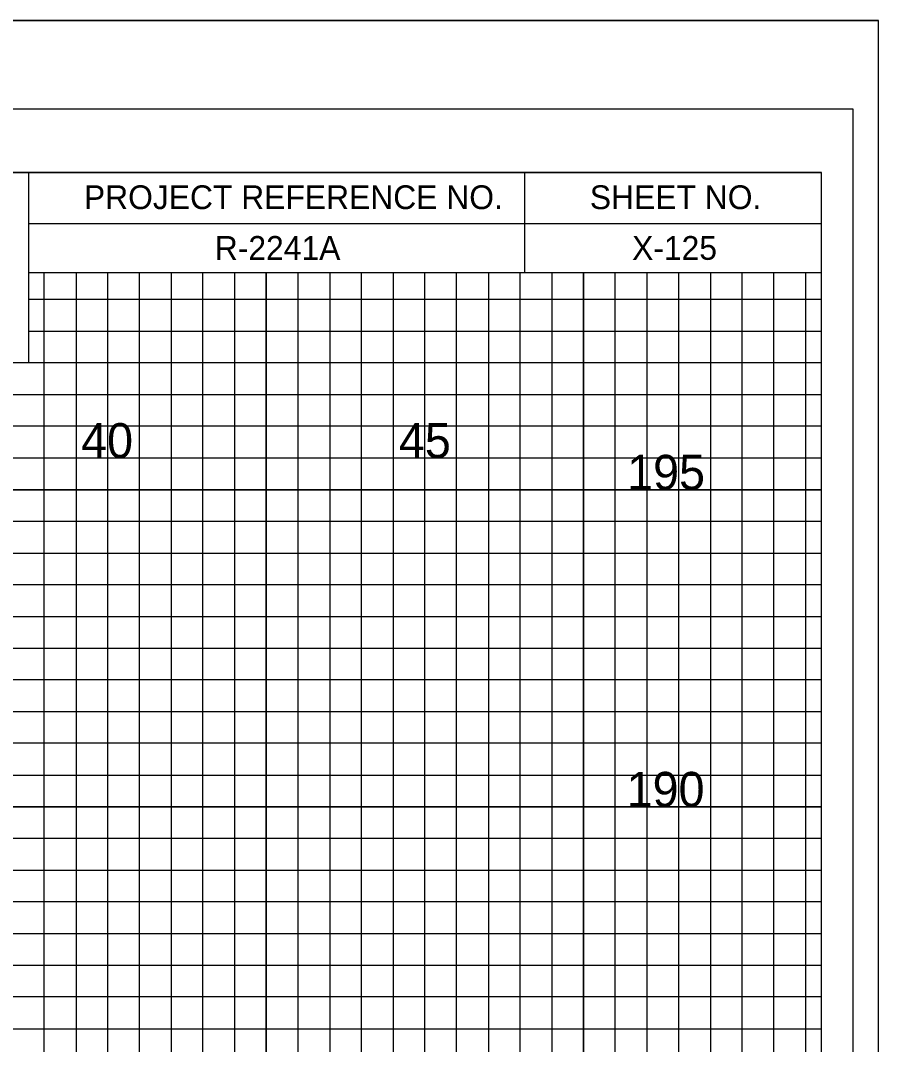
# Model space of a CAD drawing. Extents: x -4 to 103, y -2 to 138.
# Drawn here: x 89.88 to 103.4, y 51.25 to 67.4 of the extents above; entities that cross this region are included whole.
import ezdxf

# ---------------------------------------------------------------- set-up
doc = ezdxf.new("R2010")
doc.units = 0
for name, color, linetype in [('Exist XS Ground Line', 7, 'Continuous'), ('Old_Level_10', 7, 'Continuous'), ('Old_Level_16', 7, 'Continuous'), ('Old_Level_3', 7, 'Continuous'), ('Old_Level_5', 7, 'Continuous'), ('Old_Level_8', 7, 'Continuous'), ('Prop Dimension', 7, 'Continuous'), ('Prop XS Dump Level', 7, 'Continuous'), ('Prop XS SE Text', 7, 'Continuous'), ('Prop XS Subgrade Earthwork', 7, 'Continuous'), ('Prop XSC Text', 7, 'Continuous')]:
    doc.layers.add(name, color=color, linetype=linetype)

msp = doc.modelspace()

# ---------------------------------------------------------------- linework, layer by layer
at = {"layer": 'Old_Level_10'}
for p, q in [((91.25, 0), (91.25, 63.425)), ((93.75, 0), (93.75, 63.425)), ((96.25, 0), (96.25, 63.425)), ((98.75, 0), (98.75, 63.425)), ((101.25, 0), (101.25, 63.425)), ((90, 62.5), (102.5, 62.5)), ((0, 60), (102.5, 60)), ((0, 57.5), (102.5, 57.5)), ((0, 55), (102.5, 55)), ((0, 52.5), (102.5, 52.5))]:
    msp.add_line(p, q, dxfattribs=at)
at = {"layer": 'Old_Level_3'}
msp.add_line((-3.5, 67.4), (103.4, 67.4), dxfattribs=at)
at = {"layer": 'Old_Level_5'}
msp.add_lwpolyline([(103.4, 67.4), (-3.5, 67.4), (-3.5, -2.425), (103.4, -2.425)], close=True, dxfattribs=at)
at = {"layer": 'Old_Level_8'}
for points in [[(91.25, 0), (91.25, 63.425), (93.75, 63.425), (93.75, 0)], [(96.25, 0), (96.25, 63.425), (98.75, 63.425), (98.75, 0)], [(101.25, 0), (101.25, 63.425)], [(90, 62.5), (102.5, 62.5)], [(0, 57.5), (102.5, 57.5), (102.5, 60), (0, 60)], [(0, 52.5), (102.5, 52.5), (102.5, 55), (0, 55)]]:
    msp.add_lwpolyline(points, dxfattribs=at)
at = {"layer": 'Prop Dimension'}
for points in [[(90.25, 0), (90.25, 63.425), (90.75, 63.425), (90.75, 0)], [(91.75, 0), (91.75, 63.425), (92.25, 63.425), (92.25, 0)], [(92.75, 0), (92.75, 63.425), (93.25, 63.425), (93.25, 0)], [(94.25, 0), (94.25, 63.425), (94.75, 63.425), (94.75, 0)], [(95.25, 0), (95.25, 63.425), (95.75, 63.425), (95.75, 0)], [(96.75, 0), (96.75, 63.425), (97.25, 63.425), (97.25, 0)], [(97.75, 0), (97.75, 63.425), (98.25, 63.425), (98.25, 0)], [(99.25, 0), (99.25, 63.425), (99.75, 63.425), (99.75, 0)], [(100.25, 0), (100.25, 63.425)], [(100.25, 63.425), (100.75, 63.425), (100.75, 0), (101.75, 0), (101.75, 63.425), (102.25, 63.425), (102.25, 0)], [(102.5, 62), (102.5, 63), (90, 63)], [(0, 61.5), (102.5, 61.5), (102.5, 62), (0, 62)], [(0, 60.5), (102.5, 60.5), (102.5, 61), (0, 61)], [(0, 59), (102.5, 59), (102.5, 59.5), (0, 59.5)], [(0, 58), (102.5, 58), (102.5, 58.5), (0, 58.5)], [(0, 56.5), (102.5, 56.5), (102.5, 57), (0, 57)], [(0, 55.5), (102.5, 55.5), (102.5, 56), (0, 56)], [(0, 54), (102.5, 54), (102.5, 54.5), (0, 54.5)], [(0, 53), (102.5, 53), (102.5, 53.5), (0, 53.5)], [(0, 51.5), (102.5, 51.5), (102.5, 52), (0, 52)]]:
    msp.add_lwpolyline(points, dxfattribs=at)
at = {"layer": 'Prop XS SE Text'}
msp.add_lwpolyline([(103, 66), (-2.8, 66), (-2.8, -1), (103, -1)], close=True, dxfattribs=at)
at = {"layer": 'Prop XSC Text'}
for p, q in [((90, 65), (102.5, 65)), ((90, 65), (102.5, 65)), ((97.825, 63.425), (97.825, 65)), ((101.875, 65), (101.875, 65)), ((102.5, 65), (102.5, 65)), ((102.5, 63.425), (102.5, 65)), ((102.5, 65), (102.5, 65)), ((102.5, 65), (102.5, 65)), ((102.5, 63.425), (102.5, 65)), ((90, 64.2), (102.5, 64.2)), ((90, 63.425), (102.5, 63.425)), ((99.4, 63.425), (99.4, 63.425)), ((99.4, 63.425), (99.4, 63.425))]:
    msp.add_line(p, q, dxfattribs=at)
for points in [[(102.5, 65), (0, 65), (0, 0), (102.5, 0)], [(83.75, 65), (90, 65), (90, 62), (83.75, 62)]]:
    msp.add_lwpolyline(points, close=True, dxfattribs=at)

# ---------------------------------------------------------------- texts
at = {"layer": 'Exist XS Ground Line'}
msp.add_text('X-125', height=0.375, dxfattribs=at).set_placement((99.516, 63.625))
at = {"layer": 'Old_Level_16'}
for s, p in [('40', (90.831, 60.5)), ('45', (95.84, 60.5))]:
    msp.add_text(s, height=0.55, dxfattribs=at).set_placement(p)
at = {"layer": 'Prop XS Dump Level'}
msp.add_text('R-2241A', height=0.375, dxfattribs=at).set_placement((92.938, 63.625))
at = {"layer": 'Prop XS Subgrade Earthwork'}
for s, p in [('195', (99.438, 60)), ('190', (99.43, 55))]:
    msp.add_text(s, height=0.55, dxfattribs=at).set_placement(p)
at = {"layer": 'Prop XSC Text'}
for s, p in [('PROJECT REFERENCE NO.', (90.875, 64.425)), ('SHEET NO.', (98.85, 64.425))]:
    msp.add_text(s, height=0.375, dxfattribs=at).set_placement(p)

doc.saveas('drawing.dxf')
